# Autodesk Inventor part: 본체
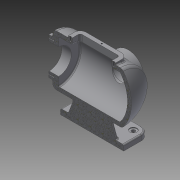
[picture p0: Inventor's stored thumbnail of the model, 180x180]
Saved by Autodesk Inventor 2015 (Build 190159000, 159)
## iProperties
Created: 2021-11
Part Number: 본체
Material: 일반
Document SubType Name: Modeling
Designer: 101256544
Density: 1 g/cm^3
Appearance: 기본값
Author: 101256544
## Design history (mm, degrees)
sketch "스케치1"
  geometry: L1 (80, -65)-(-80, -65); L2 (-80, -65)-(-80, 65); L3 (-80, 65)-(80, 65); L4 (80, 65)-(80, -65); L5 (80, -65)-(-80, 65); L6 (-80, -65)-(80, 65); 1 further point
  constraints: 12 end point, 2 midpoint, 2 parallel, 1 horizontal, 1 perpendicular
  dimensions: "d0" = 160 distance of L2.end L3.end; "d1" = 130 distance of L1.end L2.end
extrude "돌출1" new body sketch "스케치1" distance "d2" = 14; taper "d3" = 0 deg
fillet "모깎기1" dims "d4" = 20
sketch "스케치2"
  geometry: A1 r 20 centre (60, 45) between (80, 45) and (60, 65) reference; A2 r 20 centre (-60, 45) between (-60, 65) and (-80, 45) reference; A3 r 20 centre (-60, -45) between (-80, -45) and (-60, -65) reference; A4 r 20 centre (60, -45) between (60, -65) and (80, -45) reference; 1 further point
hole "구멍1" sketch "스케치2" at (-60, -45), (-60, 45), (60, -45), (60, 45) diameter "d5" = 9; stored, may be unused: countersink angle "d9" = 90 deg, drill point angle "d11" = 118 deg; dims "d6" = 6, "d7" = 18, "d8" = 2, "d10" = 8
sketch "스케치3"
  geometry: L1 (7, -50)-(-7, -50); L2 (-7, -50)-(-7, 50); L3 (-7, 50)-(7, 50); L4 (7, 50)-(7, -50); L5 (7, -50)-(-7, 50); L6 (-7, -50)-(7, 50); 1 further point
  constraints: 12 end point, 2 midpoint, 2 parallel, 1 horizontal, 1 perpendicular
  dimensions: "d12" = 14 distance of L2.end L3.end; "d13" = 100 distance of L3.end L1.start
extrude "돌출2" join sketch "스케치3" distance "d14" = 100; taper "d15" = 0 deg
feature "면 기울기1" dims angle "d16" = 20 deg
sketch "스케치4"
  geometry: L1 (60, -7)-(-60, -7); L2 (-60, -7)-(-60, 7); L3 (-60, 7)-(60, 7); L4 (60, 7)-(60, -7); L5 (60, -7)-(-60, 7); L6 (-60, -7)-(60, 7); 1 further point
  constraints: 12 end point, 2 midpoint, 2 parallel, 1 horizontal, 1 perpendicular
  dimensions: "d17" = 14 distance of L1.end L2.end; "d18" = 120 distance of L1.start L1.end
extrude "돌출3" join sketch "스케치4" distance "d19" = 100; taper "d20" = 0 deg
feature "면 기울기2" dims angle "d21" = 20 deg
sketch "스케치5"
  geometry: L1 (80, 0)-(-80, 0) reference; L2 (-80, 0)-(-80, 14) reference; L3 (-80, 14)-(-60, 14) reference; L4 (-60, 14)-(-23.603, 114) reference; L5 (-23.603, 114)-(23.603, 114) reference; L6 (23.603, 114)-(60, 14) reference; L7 (60, 14)-(80, 14) reference; L8 (80, 14)-(80, 0) reference; L9 (100, 179)-(-75.993, 179); L10 (-100, 114)-(110, 114); L11 (110, 114)-(110, 161.5); L12 (110, 161.5)-(100, 161.5); L13 (100, 161.5)-(100, 179); A1 r 100 centre (0, 114) between (-75.993, 179) and (-100, 114); 1 further point
  constraints: 10 end point, 2 horizontal, 2 point on circle, 1 centre point, 1 collinear, 1 parallel, 1 perpendicular, 1 point on line
  dimensions: "d22" = 30 distance between parallel lines of L8 L11; "d24" = 10 distance between parallel lines of L11 L13; "d25" = 47.5 distance between parallel lines of L10 L12; "d27" = 100 radius of A1; "d28" = 210 distance from line of L10.start L11; "d29" = 65 distance between parallel lines of L10 L9
revolve "회전1" sketch "스케치5" stored, may be unused: angle "d30" = 90 deg
sketch "스케치7"
  geometry: C1 r 47.5 at (0, 0) reference; C2 r 32.5 at (0, 0); 1 further point
  constraints: 1 centre point, 1 coincident
  dimensions: "d33" = 65 diameter of C2
extrude "돌출4" cut sketch "스케치7" distance "d34" = 25; taper "d35" = 0 deg
sketch "스케치6"
  geometry: L1 (80, 0)-(-80, 0) reference; L2 (-80, 0)-(-80, 14) reference; L3 (-80, 14)-(-60, 14) reference; L4 (-60, 14)-(-47.261, 49) reference; L5 (-47.261, 49)-(-75.993, 49) reference; L6 (-75.993, 179)-(100, 179) reference; L7 (100, 179)-(100, 161.5) reference; L8 (100, 161.5)-(110, 161.5) reference; L9 (110, 161.5)-(110, 146.5) reference; L10 (110, 66.5)-(100, 66.5) reference; L11 (100, 66.5)-(100, 49) reference; L12 (100, 49)-(47.261, 49) reference; L13 (47.261, 49)-(60, 14) reference; L14 (60, 14)-(80, 14) reference; L15 (80, 14)-(80, 0) reference; L16 (-71.239, 169)-(85, 169); L17 (80, 0)-(-80, 0) reference; L18 (-80, 0)-(-80, 14) reference; L19 (-80, 14)-(-60, 14) reference; L20 (-60, 14)-(-47.261, 49) reference; L21 (-47.261, 49)-(-75.993, 49) reference; L22 (-75.993, 179)-(100, 179) reference; L23 (100, 179)-(100, 161.5) reference; L24 (100, 161.5)-(110, 161.5) reference; L25 (110, 161.5)-(110, 146.5) reference; L26 (110, 66.5)-(100, 66.5) reference; L27 (100, 66.5)-(100, 49) reference; L28 (100, 49)-(47.261, 49) reference; L29 (47.261, 49)-(60, 14) reference; L30 (60, 14)-(80, 14) reference; L31 (80, 14)-(80, 0) reference; L32 (-75.993, 49)-(100, 49) reference; L33 (85, 59)-(-71.239, 59); L34 (-75.993, 49)-(-75.993, 179) reference; L35 (110, 146.5)-(85, 146.5) reference; L36 (85, 146.5)-(85, 81.5) reference; L37 (85, 81.5)-(110, 81.5) reference; L38 (110, 81.5)-(110, 66.5) reference; L39 (110, 146.5)-(85, 146.5) reference; L40 (85, 146.5)-(85, 81.5) reference; L41 (85, 81.5)-(110, 81.5) reference; L42 (110, 81.5)-(110, 66.5) reference; L43 (85, 59)-(85, 169); L44 (85, 114)-(-90, 114); A1 r 100 centre (0, 114) between (-75.993, 179) and (-75.993, 49) reference; A2 r 90 centre (0, 114) between (-71.239, 169) and (-71.239, 59); A3 r 100 centre (0, 114) between (-75.993, 179) and (-75.993, 49) reference; 1 further point
  constraints: 9 end point, 3 perpendicular, 3 point on circle, 1 centre point, 1 collinear, 1 midpoint, 1 vertical
  dimensions: "d31" = 10 radial gap between concentric circles of A1 A2; "d32" = 10 distance between parallel lines of L33 L32; "d36" = 10 distance between parallel lines of L6 L16
revolve "회전2" sketch "스케치6" stored, may be unused: angle "d37" = 90 deg
node "작업 평면1"
sketch "스케치8"
  geometry: L1 (60, 30)-(-60, 30); L2 (-60, 30)-(-60, -30); L3 (-60, -30)-(60, -30); L4 (60, -30)-(60, 30); L5 (100, -65)-(100, 65) reference; L6 (110, -47.5)-(110, 47.5) reference; 3 further points
  constraints: 8 end point, 2 midpoint, 2 parallel, 1 horizontal, 1 horizontal alignment, 1 perpendicular
  dimensions: "d39" = 120 distance of L1.start L1.end; "d40" = 60 distance of L1.end L2.end; "d41" = 50 distance between parallel lines of L4 L6
extrude "돌출5" join sketch "스케치8" stored distance "d42" = 25; taper "d43" = 0 deg
sketch "스케치9"
  geometry: L1 (-60, 30)-(60, 30) reference; L2 (-60, -30)-(-60, 30) reference; L3 (60, -30)-(-60, -30) reference; L4 (60, 30)-(60, -30) reference; L5 (50, -20)-(-50, -20); L6 (-50, -20)-(-50, 20); L7 (-50, 20)-(50, 20); L8 (50, 20)-(50, -20); 1 further point
  constraints: 8 end point, 3 other
  dimensions: "d44" = 10 distance between parallel lines of L4 L8
extrude "돌출6" cut sketch "스케치9" stored distance "d45" = 25; taper "d46" = 0 deg
fillet "모깎기2" dims "d47" = 15
fillet "모깎기3" dims "d48" = 5
sketch "스케치10"
  geometry: 5 further points
  constraints: 2 horizontal alignment, 2 vertical alignment
  dimensions: "d49" = 55 distance of point (0, 0) point (-55, 0); "d50" = 25 distance of point (0, 0) point (0, 25); "d58" = 55 distance of point (55, 0) point (0, 0); "d59" = 25 distance of point (0, 0) point (0, -25)
hole "구멍2" sketch "스케치10" at (-55, 0), (0, 25), (0, -25), (55, 0) diameter "d51" = 3.242; stored, may be unused: countersink angle "d55" = 90 deg, drill point angle "d57" = 118 deg; dims "d52" = 9, "d53" = 18, "d54" = 2, "d56" = 11
node "작업 평면2"
sketch "스케치11"
  geometry: L1 (110, 66.5)-(110, 161.5) reference; C1 r 40 at (-17, 114); 2 further points
  constraints: 1 centre point, 1 horizontal alignment, 1 midpoint
  dimensions: "d61" = 80 diameter of C1; "d62" = 127 distance from line of L1 C1.centre
extrude "돌출7" join sketch "스케치11" stored distance "d63" = 25; taper "d64" = 0 deg
sketch "스케치12"
  geometry: C1 r 40 at (0, 0) reference; 1 further point
hole "구멍3" sketch "스케치12" at (0, 0) diameter "d65" = 42; stored, may be unused: countersink angle "d69" = 90 deg, drill point angle "d71" = 118 deg; dims "d66" = 9, "d67" = 52, "d68" = 18, "d70" = 75
sketch "스케치13"
  geometry: C1 r 26 at (0, 0) reference; 2 further points
  constraints: 1 vertical alignment
  dimensions: "d72" = 32.5 distance of C1.centre point (0, 32.5)
hole "구멍4" sketch "스케치13" at (0, 32.5) diameter "d73" = 3.242; stored, may be unused: countersink angle "d77" = 90 deg, drill point angle "d79" = 118 deg; dims "d74" = 11, "d75" = 52, "d76" = 18, "d78" = 13
sketch "스케치14"
  geometry: C1 r 32.5 at (0, 0) reference; 2 further points
  constraints: 1 horizontal alignment
  dimensions: "d83" = 40 distance of C1.centre point (40, 0)
hole "구멍5" sketch "스케치14" at (40, 0) diameter "d84" = 3.242; stored, may be unused: countersink angle "d88" = 90 deg, drill point angle "d90" = 118 deg; dims "d85" = 11, "d86" = 52, "d87" = 18, "d89" = 13
fillet "모깎기4" dims "d94" = 3
fillet "모깎기5" dims "d34" = 25, "d36" = 10, "d81" = 360 deg, "d95" = 3
fillet "모깎기6" dims "d96" = 3
fillet "모깎기7" dims "d97" = 0.3
chamfer "모따기1" distance "d98" = 1; stored, may be unused: second distance "d99" = 2, angle "d100" = 45 deg
fillet "모깎기8" dims "d101" = 10
fillet "모깎기9" dims "d102" = 3
fillet "모깎기10" dims "d103" = 3
fillet "모깎기11" dims "d104" = 3
sketch "스케치15"
  geometry: L1 (120, 0)-(0, 0) reference; 3 further points
  constraints: 1 midpoint, 1 vertical alignment, 1 other
  dimensions: "d105" = 5 distance from line of L1 point (60, 5)
feature "엠보싱1" sketch "스케치15" dims "d106" = 0.5, "d107" = 0
node "솔리드1"
pattern_circular "원형 패턴1" dims angle "d81" = 360 deg
pattern_circular "원형 패턴2" dims angle "d92" = 360 deg
mirror "대칭1"
node "절단 모서리 투영1"
node "절단 모서리 투영2"
node "절단 모서리 투영3"
other parameters: "d38" = -184, "d60" = -75
